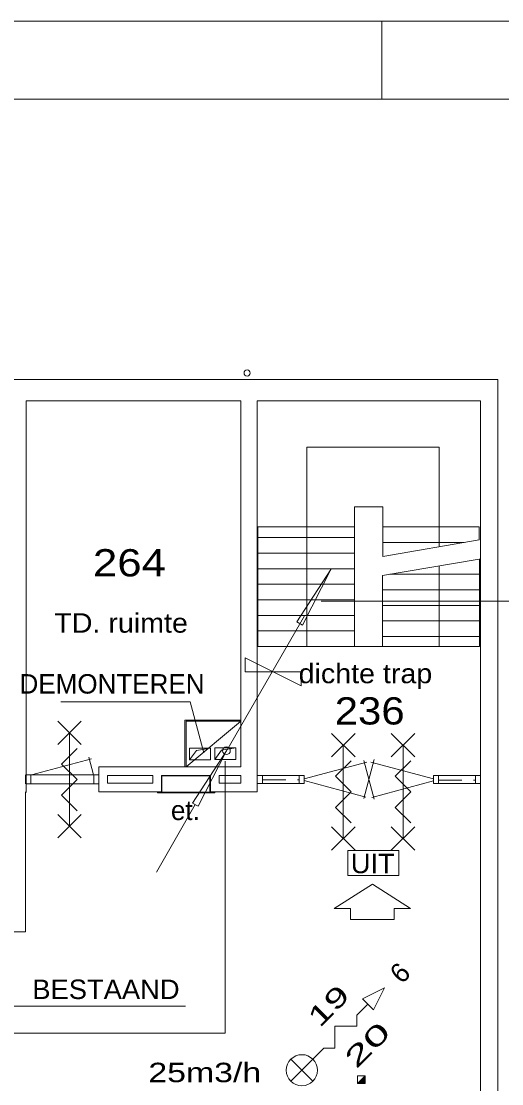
# Model space of a CAD drawing. Extents: x 295824 to 414724, y 24924 to 109024.
# Drawn here: x 326089 to 332262, y 95369 to 109024 of the extents above; entities that cross this region are included whole.
import ezdxf

# ---------------------------------------------------------------- set-up
doc = ezdxf.new("R2010")
doc.units = 0
doc.header["$LTSCALE"] = 100
doc.linetypes.add('MEDIUM_DASHED', pattern=[4.5, 3, -1.5])
for name, color, linetype, lineweight in [('1', 7, 'Continuous', 13), ('24', 7, 'Continuous', 13), ('61', 7, 'Continuous', 13)]:
    doc.layers.add(name, color=color, linetype=linetype, lineweight=lineweight)

msp = doc.modelspace()

# ---------------------------------------------------------------- hatches: boundary and pattern name
at = {"layer": '61'}
msp.add_hatch(color=256, dxfattribs=at).paths.add_polyline_path([(330408.1, 95372.4), (330508.1, 95472.4), (330508.1, 95372.4)])

# ---------------------------------------------------------------- linework, layer by layer
at = {"layer": '1'}
for p, q in [((330723.6, 108023.8), (330723.6, 109023.8)), ((327824.8, 98090.1), (328324.8, 98956.1))]:
    msp.add_line(p, q, dxfattribs=at)
for points in [[(414723.6, 109023.8), (304995.6, 109023.8), (295823.6, 109023.8)], [(304995.6, 25923.8), (413723.6, 25923.8), (413723.6, 108023.8), (304995.6, 108023.8)], [(328433.8, 99622.5), (328257.8, 100279.3), (326595.6, 100279.3)]]:
    msp.add_lwpolyline(points, dxfattribs=at)
msp.add_lwpolyline([(328724.8, 99649.1), (328360.8, 98935.1), (328288.8, 98977.1)], close=True, dxfattribs=at)
msp.add_circle((328724.8, 99648.8), 50, dxfattribs=at)
at = {"layer": '24'}
for p, q in [((329942.6, 101572.7), (337794.9, 101572.7)), ((328717.1, 99630.8), (329727.7, 101381.1)), ((328710.3, 99515.8), (328710.3, 96018.7)), ((304113.6, 96018.7), (328710.3, 96018.7))]:
    msp.add_line(p, q, dxfattribs=at)
for points in [[(330065.9, 101977.4), (329701.9, 101263.4), (329629.9, 101305.4)], [(329685.2, 100482.9), (329685.2, 100662.9), (328965.2, 100662.9), (328965.2, 100842.9)], [(328251.9, 99533.3), (328519.2, 99533.3), (328519.2, 99682.8), (328251.9, 99682.8)], [(328576.7, 99537.5), (328844, 99537.5), (328844, 99686.9), (328576.7, 99686.9)]]:
    msp.add_lwpolyline(points, close=True, dxfattribs=at)
for points in [[(328251.9, 99533.3), (328338.4, 99653.3), (328519.2, 99682.8)], [(328576.7, 99537.5), (328663.2, 99657.4), (328844, 99686.9)], [(325734.2, 96030.8), (325734.2, 96364.1), (328199.4, 96364.1)]]:
    msp.add_lwpolyline(points, dxfattribs=at)
at = {"layer": '61'}
for p, q in [((332210.1, 104417.6), (332210.1, 87553.4)), ((330368.9, 102524.7), (330368.9, 102782.6)), ((330368.9, 102782.6), (330732.6, 102782.6)), ((330732.6, 102524.7), (330732.6, 102782.6)), ((331972.5, 102524.7), (330732.6, 102524.7)), ((331972.5, 102357.4), (331972.5, 102524.7)), ((329129, 102388.3), (330368.9, 102388.3)), ((330732.6, 102146.2), (331972.5, 102357.4)), ((331780.5, 102324.7), (330732.6, 102324.7)), ((329129, 102188.3), (330368.9, 102188.3)), ((330729.7, 101899.9), (331972.5, 102111.6)), ((331459.8, 102024.2), (331459.8, 100990.2)), ((329129, 101988.3), (330368.9, 101988.3)), ((331975.6, 101916.3), (330826.3, 101916.3)), ((329129, 101788.3), (330368.9, 101788.3)), ((331975.6, 101716.3), (330729.7, 101716.3)), ((329129, 101588.3), (330368.9, 101588.3)), ((331975.6, 101516.3), (330729.7, 101516.3)), ((329129, 101388.3), (330368.9, 101388.3)), ((329129, 101188.3), (330368.9, 101188.3)), ((331975.6, 101316.3), (330729.7, 101316.3)), ((331975.6, 101116.3), (330729.7, 101116.3)), ((329129, 100988.3), (330368.9, 100988.3)), ((326857.8, 100028.2), (326557.8, 99728.2)), ((326557.8, 100028.2), (326857.8, 99728.2)), ((328910.1, 100042.6), (328190.6, 100042.6)), ((328190.6, 100042.6), (328190.6, 99443.9)), ((328207.1, 99443.8), (328906.1, 100023.8)), ((326707.8, 98678.2), (326707.8, 99878.2)), ((330376.8, 99870.8), (330076.8, 99570.8)), ((330076.8, 99870.8), (330376.8, 99570.8)), ((331143.5, 99870.8), (330843.5, 99570.8)), ((330843.5, 99870.8), (331143.5, 99570.8)), ((330226.8, 98520.8), (330226.8, 99720.8)), ((330993.5, 98520.8), (330993.5, 99720.8)), ((326218.7, 99339.4), (326991.5, 99546.4)), ((327017.2, 99340), (326956.4, 99566.9)), ((328910.1, 99442.6), (327087.4, 99442.6)), ((327087.4, 99122.6), (327087.4, 99442.6)), ((329725.3, 99287.4), (330529.4, 99502.9)), ((330621.8, 99028), (330488.5, 99525.4)), ((330489.1, 99032.9), (330623.8, 99535.6)), ((330578.4, 99502.9), (331383.5, 99287.2)), ((326142.6, 99224.8), (326142.6, 99338.8)), ((326151.2, 99338.8), (327086.5, 99338.8)), ((326210.9, 99224.8), (326210.9, 99338.8)), ((327019.5, 99224.8), (327019.5, 99338.8)), ((327086.5, 99224.8), (327086.5, 99338.8)), ((327196.2, 99232.6), (327196.2, 99332.6)), ((327780.1, 99332.6), (327196.2, 99332.6)), ((327780.1, 99232.6), (327780.1, 99332.6)), ((327890.1, 99122.6), (327890.1, 99332.6)), ((328520.1, 99332.6), (327890.1, 99332.6)), ((327895, 99116.1), (327895, 99327.8)), ((327895, 99327.8), (328510.1, 99327.8)), ((328510.1, 99116.1), (328510.1, 99327.8)), ((328520.1, 99122.6), (328520.1, 99332.6)), ((328908.2, 99332.6), (328630.1, 99332.6)), ((328630.1, 99232.6), (328630.1, 99332.6)), ((328908.2, 99232.6), (328908.2, 99332.6)), ((329120.8, 99328.4), (329723.3, 99328.4)), ((329186.3, 99228.4), (329186.3, 99328.4)), ((329657.8, 99228.4), (329657.8, 99328.4)), ((329723.3, 99228.4), (329723.3, 99328.4)), ((331384.7, 99228.4), (331384.7, 99328.4)), ((331384.7, 99328.4), (331990.1, 99328.4)), ((331451.5, 99228.5), (331451.5, 99327.5)), ((331923.1, 99228.1), (331923.1, 99328.1)), ((327086.5, 99224.8), (326151.2, 99224.8)), ((327196.2, 99232.6), (327780.1, 99232.6)), ((328630.1, 99232.6), (328908.2, 99232.6)), ((329120.8, 99228.4), (329723.3, 99228.4)), ((329723.4, 99264.2), (330517.1, 99051.5)), ((330593.7, 99049.5), (331383.5, 99261.2)), ((331384.7, 99228.4), (331990.1, 99228.4)), ((326141.5, 97322.6), (326141.5, 99122.6)), ((327087.4, 99122.6), (327890.1, 99122.6)), ((327840.7, 99115.8), (328577.6, 99115.8)), ((327840.7, 99105.8), (327840.7, 99115.8)), ((327840.7, 99105.8), (328577.6, 99105.8)), ((328520.1, 99122.6), (329120.1, 99122.6)), ((328577.6, 99105.8), (328577.6, 99115.8)), ((331990.1, 99122.6), (331990.1, 94659.1)), ((326857.8, 98828.2), (326557.8, 98528.2)), ((326557.8, 98828.2), (326857.8, 98528.2)), ((330376.8, 98670.8), (330076.8, 98370.8)), ((330076.8, 98670.8), (330376.8, 98370.8)), ((331143.5, 98670.8), (330843.5, 98370.8)), ((330843.5, 98670.8), (331143.5, 98370.8)), ((325931.5, 97322.6), (326141.5, 97322.6)), ((329835.6, 95401.3), (329552.8, 95684.1))]:
    msp.add_line(p, q, dxfattribs=at)
at = {"layer": '61', "linetype": 'MEDIUM_DASHED'}
for p, q in [((329188.3, 99274.8), (329658.2, 99274.8)), ((331450.5, 99272.3), (331922.9, 99272.3))]:
    msp.add_line(p, q, dxfattribs=at)
at = {"layer": '61'}
for points in [[(301796.6, 92184.5), (301820.1, 104417.6), (332210.1, 104417.6)], [(326150.1, 99110.7), (326150.1, 104147.6), (328910.1, 104147.6), (328910.1, 99442.6)], [(329120.1, 99122.6), (329120.1, 104147.6), (331990.1, 104147.6), (331990.1, 99120.9)], [(329757.2, 100988.3), (329757.2, 103549), (331460, 103549), (331460, 102270.1)], [(331972.5, 102524.7), (330732.6, 102524.7), (330732.6, 102146.2)], [(330729.7, 100990.2), (331975.6, 100990.2), (331975.6, 102116.3)], [(330729.7, 101899.9), (330729.7, 100990.2), (330368.9, 100988.3)], [(328910.1, 100027.6), (328207.4, 100027.6), (328207.4, 99442.6)], [(326807.8, 98878.2), (326607.8, 99078.2), (326807.8, 99278.2), (326607.8, 99478.2), (326807.8, 99678.2)], [(330326.8, 98720.8), (330126.8, 98920.8), (330326.8, 99120.8), (330126.8, 99320.8), (330326.8, 99520.8)], [(331093.5, 98720.8), (330893.5, 98920.8), (331093.5, 99120.8), (330893.5, 99320.8), (331093.5, 99520.8)], [(329552.8, 95401.3), (329977, 95825.6), (330118.4, 95825.5), (330118.4, 96108.4), (330401.3, 96108.4), (330401.3, 96249.8), (330542.7, 96391.2)], [(330508.1, 95472.4), (330508.1, 95372.4), (330408.1, 95372.4)]]:
    msp.add_lwpolyline(points, dxfattribs=at)
for points in [[(330368.9, 102524.7), (329129, 102524.7), (329129, 100988.3), (330368.9, 100988.3)], [(330284.1, 98044.6), (330940.7, 98044.6), (330940.7, 98365.6), (330284.1, 98365.6)], [(330881, 97479.4), (330321, 97479.4), (330321, 97619.4), (330111, 97619.4), (330601, 97934.4), (331091, 97619.4), (330881, 97619.4)], [(330472, 96461.9), (330613.4, 96320.5), (330754.8, 96603.4)], [(330508.1, 95472.4), (330408.1, 95472.4), (330408.1, 95372.4)], [(330408.1, 95372.4), (330508.1, 95472.4), (330508.1, 95372.4)]]:
    msp.add_lwpolyline(points, close=True, dxfattribs=at)
for centre, radius in [((328990.8, 104502.7), 40), ((329694.2, 95542.7), 200)]:
    msp.add_circle(centre, radius, dxfattribs=at)

# ---------------------------------------------------------------- texts
at = {"layer": '24'}
msp.add_text('DEMONTEREN', height=250, dxfattribs=at).set_placement((326066.4, 100383.2))
for s, width, p in [('BESTAAND', 1.05, (326231, 96457.7)), ('25m3/h', 1.3, (327721.8, 95389))]:
    msp.add_text(s, height=250, dxfattribs=dict(at, width=width)).set_placement(p)
at = {"layer": '61'}
for s, height, width, p in [('264', 350, 1.2, (327010, 101889.5)), ('TD. ruimte', 250, 1.1, (326513.7, 101166)), ('dichte trap', 250, 1.1, (329652.6, 100516.4)), ('236', 350, 1.15, (330116.5, 99985.9)), ('UIT', 250, 1.05, (330322.3, 98075.2))]:
    msp.add_text(s, height=height, dxfattribs=dict(at, width=width)).set_placement(p)
msp.add_text('et.', height=250, dxfattribs=at).set_placement((328012, 98758))
msp.add_text('6', height=250, rotation=45, dxfattribs=at).set_placement((330977.5, 96641.1))
for s, width, p in [('19', 1.55, (329921.2, 96079.6)), ('20', 1.75, (330393.5, 95551.1))]:
    msp.add_text(s, height=250, rotation=45, dxfattribs=dict(at, width=width)).set_placement(p)

doc.saveas('drawing.dxf')
